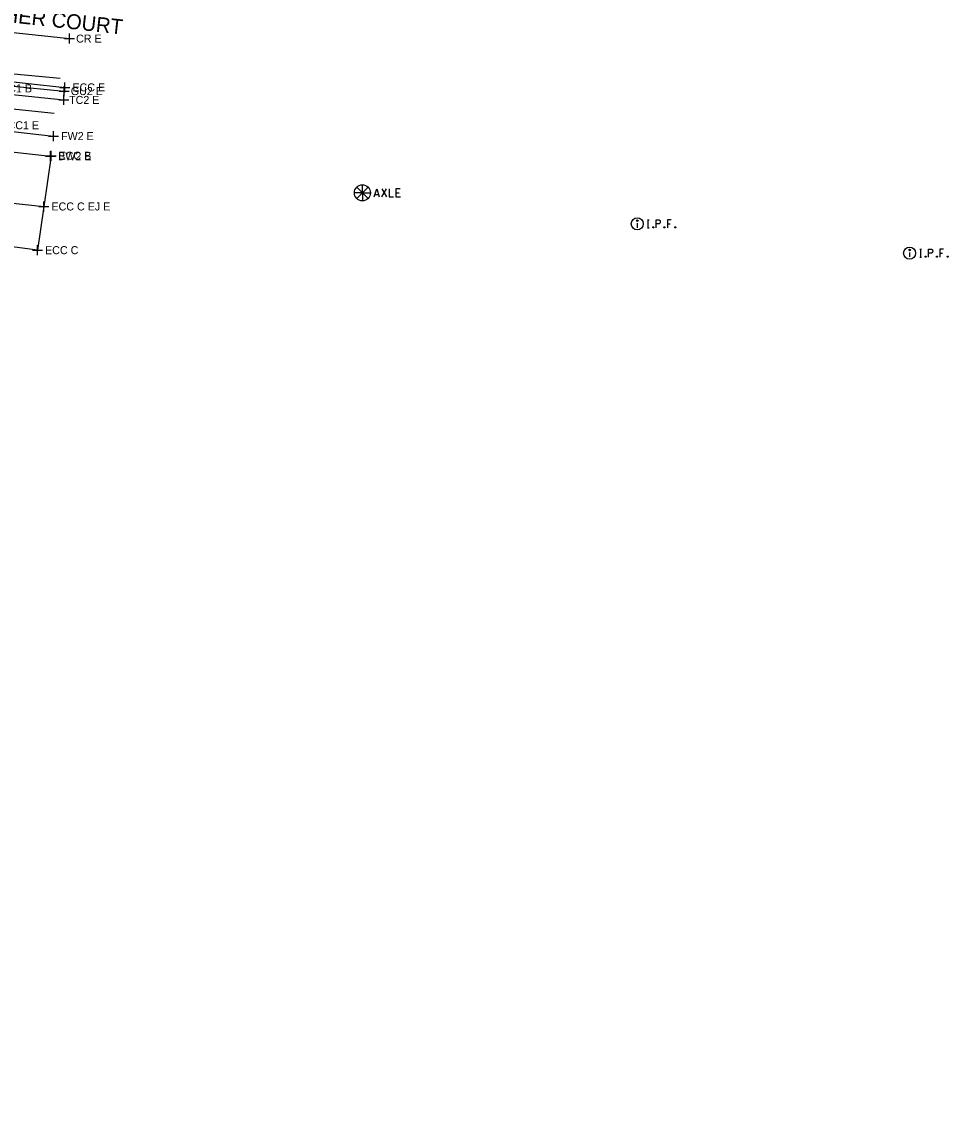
# Model space of a CAD drawing. Extents: x 1363693 to 1365209, y 422201 to 424153.
# Drawn here: x 1364355.7 to 1364540.7, y 423227.7 to 423446.2 of the extents above; entities that cross this region are included whole.
import ezdxf

# ---------------------------------------------------------------- set-up
doc = ezdxf.new("R2010")
doc.units = 0
for name, color, linetype in [('BASELINE-CL-RW', 7, 'Continuous'), ('O-ALGN-BASELINE-WERK-CL-RW', 7, 'Continuous'), ('O-ALGN-TEXT-BASELINE-WERK-CL-RW', 7, 'Continuous'), ('OWNERS', 7, 'Continuous'), ('PV_X_Driveway', 7, 'Continuous'), ('PV_X_Joint', 7, 'Continuous'), ('RD_X_Text', 7, 'Continuous'), ('SV_X_Mon_Cells_Found', 7, 'Continuous'), ('SV_X_Original_Ground', 7, 'Continuous'), ('SV_X_Shot_Marker', 7, 'Continuous'), ('UT_X_Gas', 7, 'Continuous'), ('UT_X_Sanitary_Line', 7, 'Continuous')]:
    doc.layers.add(name, color=color, linetype=linetype)

msp = doc.modelspace()

# ---------------------------------------------------------------- linework, layer by layer
at = {"layer": 'BASELINE-CL-RW'}
msp.add_lwpolyline([(1364303.24, 423434.61), (1364304.52, 423434.85), (1364304.52, 423434.85), (1364305, 423434.94), (1364305, 423434.94), (1364308.59, 423435.59), (1364308.59, 423435.59), (1364309.19, 423435.69), (1364309.19, 423435.69), (1364309.71, 423435.76), (1364309.71, 423435.76), (1364313.01, 423435.94), (1364313.01, 423435.94), (1364313.56, 423435.94), (1364313.56, 423435.94), (1364314.9, 423435.88), (1364314.9, 423435.88), (1364317.89, 423435.64), (1364320.87, 423435.38), (1364323.05, 423435.13), (1364342.14, 423432.9), (1364364.04, 423430.58)], dxfattribs=at)
at = {"layer": 'O-ALGN-BASELINE-WERK-CL-RW'}
msp.add_lwpolyline([(1364294.87, 423449.63), (1364303.73, 423449.19), (1364309.83, 423448.67), (1364318.89, 423447.88), (1364343.93, 423445.16), (1364365.18, 423442.85)], dxfattribs=at)
at = {"layer": 'O-ALGN-TEXT-BASELINE-WERK-CL-RW'}
for points in [[(1364305, 423434.94), (1364306.57, 423429.71), (1364317.13, 423428.32), (1364342.63, 423425.53), (1364362, 423423.37)], [(1364342.22, 423421.51), (1364361.42, 423419.34)]]:
    msp.add_lwpolyline(points, dxfattribs=at)
at = {"layer": 'OWNERS'}
for points in [[(1364320.74, 423437.54), (1364323.31, 423437.42), (1364342.4, 423435.49), (1364364.28, 423433.1)], [(1364321.11, 423435.91), (1364323.21, 423436.32), (1364342.33, 423434.49), (1364364.11, 423432.36)]]:
    msp.add_lwpolyline(points, dxfattribs=at)
at = {"layer": 'PV_X_Driveway'}
for points in [[(1364320.74, 423437.54), (1364323.31, 423437.42), (1364342.4, 423435.49), (1364364.28, 423433.1)], [(1364321.11, 423435.91), (1364323.21, 423436.32), (1364342.33, 423434.49), (1364364.11, 423432.36)], [(1364361.5, 423419.44), (1364360.08, 423409.3), (1364358.81, 423400.56), (1364340.17, 423403.02)]]:
    msp.add_lwpolyline(points, dxfattribs=at)
at = {"layer": 'PV_X_Joint'}
msp.add_line((1364341.14, 423411.37), (1364360.08, 423409.3), dxfattribs=at)
at = {"layer": 'SV_X_Mon_Cells_Found'}
for p, q in [((1364423.7, 423412.02), (1364423.7, 423413.62)), ((1364423.7, 423412.02), (1364422.1, 423412.02)), ((1364422.56, 423413.15), (1364423.7, 423412.02)), ((1364422.56, 423410.89), (1364423.7, 423412.02)), ((1364423.7, 423412.02), (1364424.83, 423413.15)), ((1364423.7, 423412.02), (1364425.3, 423412.02)), ((1364423.7, 423412.02), (1364423.7, 423410.42)), ((1364423.7, 423412.02), (1364424.83, 423410.89)), ((1364478.61, 423405.94), (1364478.61, 423405.05)), ((1364533.02, 423400.08), (1364533.02, 423399.2))]:
    msp.add_line(p, q, dxfattribs=at)
for points in [[(1364426.07, 423411.22), (1364426.57, 423412.82), (1364427.07, 423411.22)], [(1364426.94, 423411.6), (1364426.2, 423411.6)], [(1364427.57, 423412.82), (1364428.53, 423411.22)], [(1364427.57, 423411.22), (1364428.53, 423412.82)], [(1364429.03, 423412.82), (1364429.03, 423411.22), (1364429.9, 423411.22)], [(1364431.27, 423412.82), (1364430.4, 423412.82), (1364430.4, 423411.22), (1364431.34, 423411.22)], [(1364430.4, 423412.02), (1364431.02, 423412.02)], [(1364480.64, 423406.62), (1364480.99, 423406.62)], [(1364480.64, 423405.02), (1364480.99, 423405.02)], [(1364480.81, 423405.02), (1364480.81, 423406.62)], [(1364481.77, 423405.24), (1364481.83, 423405.24), (1364481.86, 423405.21), (1364481.89, 423405.16), (1364481.89, 423405.1), (1364481.86, 423405.05), (1364481.83, 423405.02), (1364481.77, 423405.02), (1364481.74, 423405.05), (1364481.71, 423405.1), (1364481.71, 423405.16), (1364481.74, 423405.21), (1364481.77, 423405.24)], [(1364482.38, 423405.02), (1364482.38, 423406.62), (1364482.91, 423406.62), (1364482.96, 423406.61), (1364483.04, 423406.58), (1364483.07, 423406.56), (1364483.1, 423406.53), (1364483.15, 423406.47), (1364483.18, 423406.41), (1364483.2, 423406.31), (1364483.2, 423406.15), (1364483.19, 423406.1), (1364483.17, 423406.03), (1364483.13, 423405.94), (1364483.08, 423405.9), (1364483.05, 423405.88), (1364482.99, 423405.85), (1364482.91, 423405.84), (1364482.38, 423405.84)], [(1364484.02, 423405.24), (1364484.07, 423405.24), (1364484.11, 423405.21), (1364484.14, 423405.16), (1364484.14, 423405.1), (1364484.11, 423405.05), (1364484.07, 423405.02), (1364484.02, 423405.02), (1364483.99, 423405.05), (1364483.95, 423405.1), (1364483.95, 423405.16), (1364483.99, 423405.21), (1364484.02, 423405.24)], [(1364485.39, 423406.62), (1364484.63, 423406.62), (1364484.63, 423405.02)], [(1364484.63, 423405.84), (1364485.17, 423405.84)], [(1364486.17, 423405.24), (1364486.22, 423405.24), (1364486.26, 423405.21), (1364486.29, 423405.16), (1364486.29, 423405.1), (1364486.26, 423405.05), (1364486.22, 423405.02), (1364486.17, 423405.02), (1364486.14, 423405.05), (1364486.1, 423405.1), (1364486.1, 423405.16), (1364486.14, 423405.21), (1364486.17, 423405.24)], [(1364535.05, 423400.76), (1364535.4, 423400.76)], [(1364535.23, 423399.16), (1364535.23, 423400.76)], [(1364536.79, 423399.16), (1364536.79, 423400.76), (1364537.32, 423400.76), (1364537.38, 423400.75), (1364537.46, 423400.72), (1364537.49, 423400.7), (1364537.52, 423400.67), (1364537.57, 423400.61), (1364537.6, 423400.55), (1364537.62, 423400.45), (1364537.62, 423400.3), (1364537.61, 423400.25), (1364537.59, 423400.17), (1364537.54, 423400.08), (1364537.5, 423400.04), (1364537.47, 423400.02), (1364537.41, 423399.99), (1364537.32, 423399.98), (1364536.79, 423399.98)], [(1364539.8, 423400.76), (1364539.04, 423400.76), (1364539.04, 423399.16)], [(1364535.05, 423399.16), (1364535.4, 423399.16)], [(1364536.19, 423399.38), (1364536.24, 423399.38), (1364536.28, 423399.35), (1364536.31, 423399.3), (1364536.31, 423399.24), (1364536.28, 423399.19), (1364536.24, 423399.16), (1364536.19, 423399.16), (1364536.15, 423399.19), (1364536.12, 423399.24), (1364536.12, 423399.3), (1364536.15, 423399.35), (1364536.19, 423399.38)], [(1364538.44, 423399.38), (1364538.49, 423399.38), (1364538.52, 423399.35), (1364538.56, 423399.3), (1364538.56, 423399.24), (1364538.52, 423399.19), (1364538.49, 423399.16), (1364538.44, 423399.16), (1364538.4, 423399.19), (1364538.37, 423399.24), (1364538.37, 423399.3), (1364538.4, 423399.35), (1364538.44, 423399.38)], [(1364539.04, 423399.98), (1364539.58, 423399.98)], [(1364540.59, 423399.38), (1364540.64, 423399.38), (1364540.67, 423399.35), (1364540.71, 423399.3), (1364540.71, 423399.24), (1364540.67, 423399.19), (1364540.64, 423399.16), (1364540.59, 423399.16), (1364540.55, 423399.19), (1364540.52, 423399.24), (1364540.52, 423399.3), (1364540.55, 423399.35), (1364540.59, 423399.38)]]:
    msp.add_lwpolyline(points, dxfattribs=at)
for centre, radius in [((1364423.7, 423412.02), 1.6), ((1364423.7, 423412.02), 0.204), ((1364478.61, 423405.82), 1.2), ((1364478.61, 423406.47), 0.16), ((1364533.02, 423399.96), 1.2), ((1364533.02, 423400.61), 0.16)]:
    msp.add_circle(centre, radius, dxfattribs=at)
at = {"layer": 'SV_X_Original_Ground'}
for p, q in [((1364365.18, 423441.85), (1364365.18, 423443.85)), ((1364364.18, 423442.85), (1364366.18, 423442.85))]:
    msp.add_line(p, q, dxfattribs=at)
at = {"layer": 'SV_X_Shot_Marker'}
for p, q in [((1364363.28, 423433.1), (1364365.28, 423433.1)), ((1364364.11, 423431.36), (1364364.11, 423433.36)), ((1364364.28, 423432.1), (1364364.28, 423434.1)), ((1364363.11, 423432.36), (1364365.11, 423432.36)), ((1364364.04, 423429.58), (1364364.04, 423431.58)), ((1364363.04, 423430.58), (1364365.04, 423430.58)), ((1364362, 423422.37), (1364362, 423424.37)), ((1364361, 423423.37), (1364363, 423423.37)), ((1364361.42, 423418.34), (1364361.42, 423420.34)), ((1364361.5, 423418.44), (1364361.5, 423420.44)), ((1364360.42, 423419.34), (1364362.42, 423419.34)), ((1364360.5, 423419.44), (1364362.5, 423419.44)), ((1364359.08, 423409.3), (1364361.08, 423409.3)), ((1364360.08, 423408.3), (1364360.08, 423410.3)), ((1364357.81, 423400.56), (1364359.81, 423400.56)), ((1364358.81, 423399.56), (1364358.81, 423401.56))]:
    msp.add_line(p, q, dxfattribs=at)
at = {"layer": 'UT_X_Gas'}
msp.add_lwpolyline([(1364225.48, 423227.68), (1364230.29, 423271.65), (1364244.95, 423427.25), (1364255.63, 423426.64), (1364257.03, 423438.97), (1364362.14, 423427.96)], dxfattribs=at)
at = {"layer": 'UT_X_Sanitary_Line'}
msp.add_lwpolyline([(1364253.21, 423263.58), (1364270.77, 423443.61), (1364363.35, 423434.92)], dxfattribs=at)

# ---------------------------------------------------------------- texts
at = {"layer": 'RD_X_Text'}
msp.add_text('HEATHER COURT', height=3, rotation=353.8084, dxfattribs=at).set_placement((1364341.33, 423447.39))
at = {"layer": 'SV_X_Original_Ground'}
msp.add_text('CR E', height=1.6, dxfattribs=at).set_placement((1364366.51, 423442.05))
at = {"layer": 'SV_X_Shot_Marker'}
for s, p in [('TC2 C ECC1 B', (1364343.21, 423432.1)), ('GU2 E', (1364365.45, 423431.56)), ('ECC E', (1364365.78, 423432.3)), ('TC2 E', (1364365.11, 423429.79)), ('FW2 C ECC1 E', (1364344.14, 423424.73)), ('FW2 E', (1364363.5, 423422.57)), ('BW2 E', (1364362.92, 423418.54)), ('ECC B', (1364363, 423418.64)), ('ECC C EJ E', (1364361.58, 423408.5)), ('ECC C', (1364360.31, 423399.76))]:
    msp.add_text(s, height=1.6, dxfattribs=at).set_placement(p)

doc.saveas('drawing.dxf')
